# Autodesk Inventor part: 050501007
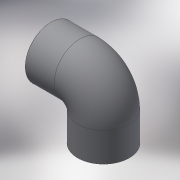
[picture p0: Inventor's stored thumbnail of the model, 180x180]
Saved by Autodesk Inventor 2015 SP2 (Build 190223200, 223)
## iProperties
Created: 2017-10
Part Number: 050501007
Material: Generic
Description: PLASSON THREADED 90° ELBOW PVC 3/4"
Document SubType Name: Modeling
Designer: KIM
Density: 1 g/cm^3
Appearance: Default
Author: KIM
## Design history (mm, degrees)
derived "050501.ipt"
feature "Solid1::050501.ipt"
tag "TaggingFeature1"
body "Solid1"
other parameters: "d7" = 0.24117, "d10" = 35, "d13" = 90 deg, "d19" = 90 deg, "d20" = 24.117, "d21" = 18, "d22" = 0, "d24" = 90 deg, "d26" = 21.7053, "d27" = 90 deg, "d28" = 18, "G_" = 24.117, "lt_" = 18
